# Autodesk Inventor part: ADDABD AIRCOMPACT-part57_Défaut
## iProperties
Shininess: 64.0
Length Units: 11269
Angle Units: 11279
Time Units: 11290
Mass Units: 11283
Length Display Precision: 3
Angle Display Precision: 2
Compacted: True
Part Number: ADDABD AIRCOMPACT-part57_Défaut
Document SubType Name: Modeling
Created: 2006-01
Material: Par défaut
Designer: riri
Density: 0.0
Volumn: 0.0
Area: 0.0
PropertySet Name: Model Information
Control State: 0
Master: False
Checked Out: False
Author: riri
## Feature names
1. Base1
